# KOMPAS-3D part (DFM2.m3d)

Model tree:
1. Эскиз:1
2. Операция выдавливания:1
     Расстояние 1 = 5.6
3. Эскиз:2
4. Эскиз:3
5. Эскиз:4
6. Эскиз:5
7. Эскиз:6
8. Эскиз:7
9. Операция выдавливания:2
     Расстояние 1 = 0.85; Угол 1 = 45
10. Операция выдавливания:3
     Расстояние 1 = 0.85; Угол 1 = 45
11. Операция выдавливания:4
     Расстояние 1 = 0.85; Угол 1 = 45
12. Вырезать элемент выдавливания:1
     Расстояние 1 = 0.85; Угол 1 = 45
13. Вырезать элемент выдавливания:2
     Расстояние 1 = 0.85; Угол 1 = 45
14. Вырезать элемент выдавливания:3
     Расстояние 1 = 0.85; Угол 1 = 45
15. Эскиз:8
16. Эскиз:9
17. Эскиз:10
18. Эскиз:11
19. Эскиз:12
20. Эскиз:13
21. Операция выдавливания:5
     Расстояние 1 = 0.85; Угол 1 = 45
22. Операция выдавливания:6
     Расстояние 1 = 0.85; Угол 1 = 45
23. Операция выдавливания:7
     Расстояние 1 = 0.85; Угол 1 = 45
24. Вырезать элемент выдавливания:4
     Расстояние 1 = 0.85; Угол 1 = 45
25. Вырезать элемент выдавливания:5
     Расстояние 1 = 0.85; Угол 1 = 45
26. Вырезать элемент выдавливания:6
     Расстояние 1 = 0.85; Угол 1 = 45
27. Массив по концентрической сетке:1  (with: Операция выдавливания:5, Операция выдавливания:6, Операция выдавливания:7, Вырезать элемент выдавливания:4, Вырезать элемент выдавливания:5, Вырезать элемент выдавливания:6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)  (6 pattern instances)
     Геометрический массив = 5; Шаг 2 = 360; Номер 2 = 1
28. Скругление:1
     Радиус = 2.8
29. Фаска:1
     Угол = 40; Длина 1 = 0.8; Длина 2 = 0.67128
30. Скругление:2
     Радиус = 0.9
